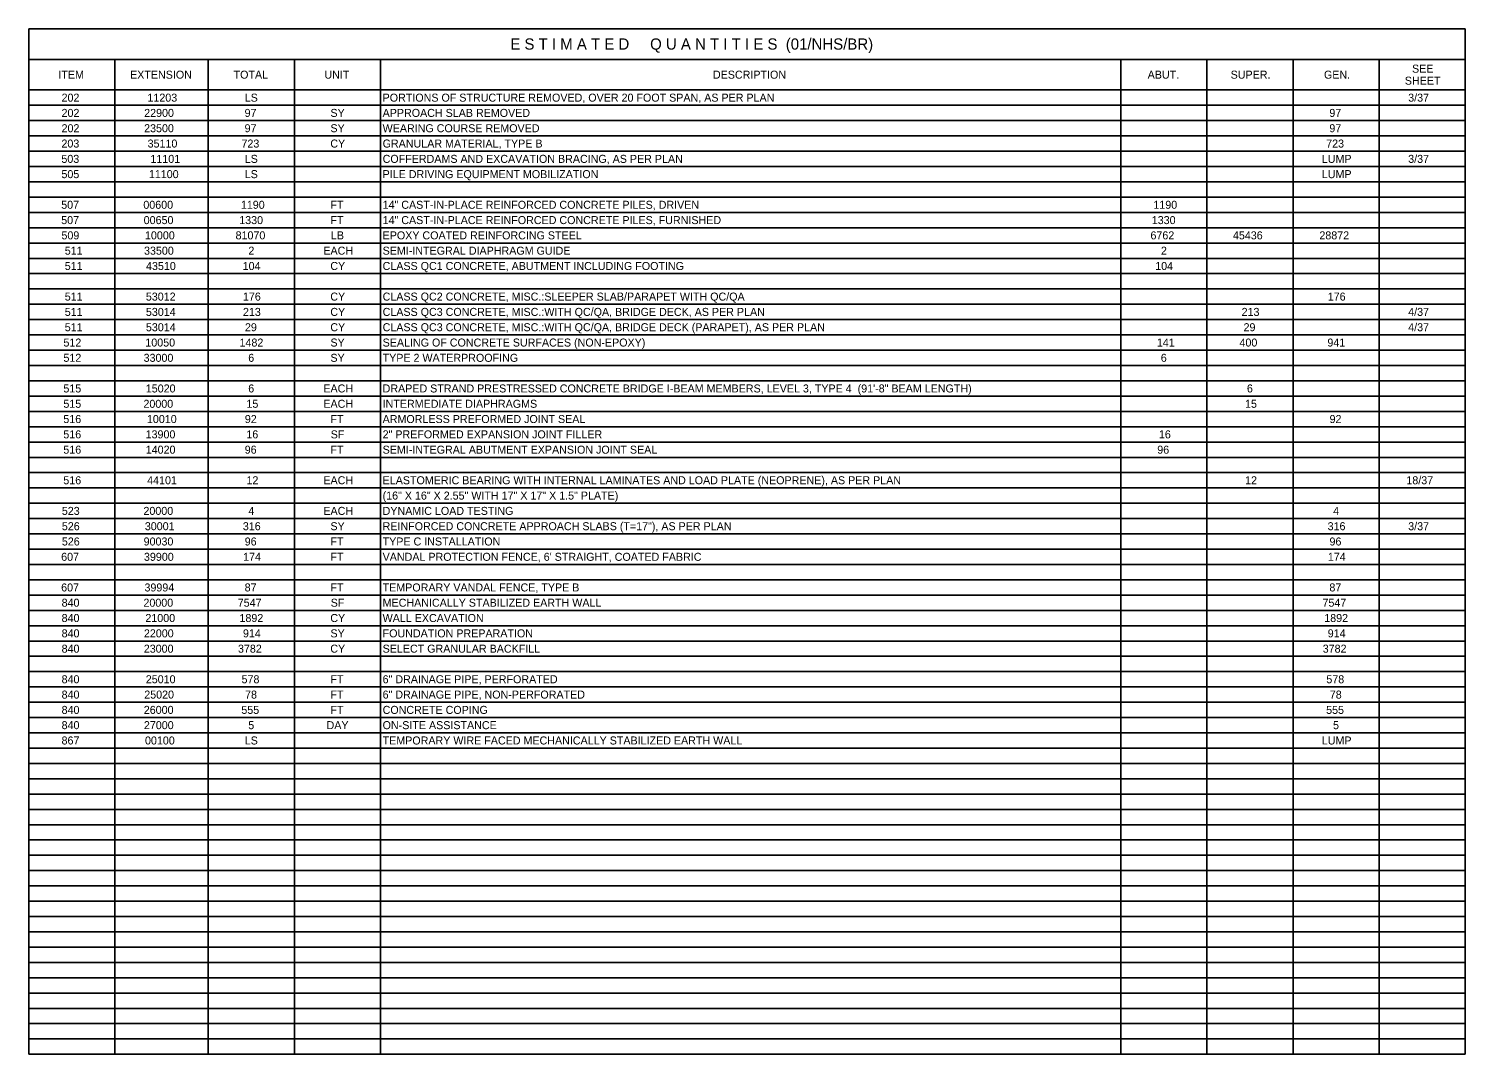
# Model space of a CAD drawing. Extents: x -1059 to 109, y -40 to 149.
# Drawn here: x -1059.2 to -1034.06, y 130.87 to 148.81 of the extents above; entities that cross this region are included whole.
import ezdxf

# ---------------------------------------------------------------- set-up
doc = ezdxf.new("R2010")
doc.units = 0
doc.layers.add('Sheet_Label_Str_Wt0', color=7, linetype='Continuous')

msp = doc.modelspace()

# ---------------------------------------------------------------- linework, layer by layer
at = {"layer": 'Sheet_Label_Str_Wt0'}
for p, q in [((-1059.195, 148.805), (-1059.195, 148.805)), ((-1059.195, 148.805), (-1034.058, 148.805)), ((-1059.195, 130.866), (-1059.195, 148.805)), ((-1034.058, 130.866), (-1034.058, 148.805)), ((-1059.195, 148.27), (-1034.058, 148.27)), ((-1057.689, 130.866), (-1057.689, 148.27)), ((-1056.053, 130.866), (-1056.053, 148.27)), ((-1054.547, 130.866), (-1054.547, 148.27)), ((-1053.04, 130.866), (-1053.04, 148.27)), ((-1040.085, 130.866), (-1040.085, 148.27)), ((-1038.579, 130.866), (-1038.579, 148.27)), ((-1037.072, 130.866), (-1037.072, 148.27)), ((-1035.565, 130.866), (-1035.565, 148.27)), ((-1059.195, 147.734), (-1034.058, 147.734)), ((-1059.195, 147.467), (-1034.058, 147.467)), ((-1059.195, 147.199), (-1034.058, 147.199)), ((-1059.195, 146.931), (-1034.058, 146.931)), ((-1059.195, 146.663), (-1034.058, 146.663)), ((-1059.195, 146.396), (-1034.058, 146.396)), ((-1059.195, 146.128), (-1034.058, 146.128)), ((-1059.195, 145.86), (-1034.058, 145.86)), ((-1059.195, 145.592), (-1034.058, 145.592)), ((-1059.195, 145.325), (-1034.058, 145.325)), ((-1059.195, 145.057), (-1034.058, 145.057)), ((-1059.195, 144.789), (-1034.058, 144.789)), ((-1059.195, 144.521), (-1034.058, 144.521)), ((-1059.195, 144.254), (-1034.058, 144.254)), ((-1059.195, 143.986), (-1034.058, 143.986)), ((-1059.195, 143.718), (-1034.058, 143.718)), ((-1059.195, 143.45), (-1034.058, 143.45)), ((-1059.195, 143.183), (-1034.058, 143.183)), ((-1059.195, 142.915), (-1034.058, 142.915)), ((-1059.195, 142.647), (-1034.058, 142.647)), ((-1059.195, 142.379), (-1034.058, 142.379)), ((-1059.195, 142.112), (-1034.058, 142.112)), ((-1059.195, 141.844), (-1034.058, 141.844)), ((-1059.195, 141.576), (-1034.058, 141.576)), ((-1059.195, 141.308), (-1034.058, 141.308)), ((-1059.195, 141.041), (-1034.058, 141.041)), ((-1059.195, 140.773), (-1034.058, 140.773)), ((-1059.195, 140.505), (-1034.058, 140.505)), ((-1059.195, 140.237), (-1034.058, 140.237)), ((-1059.195, 139.97), (-1034.058, 139.97)), ((-1059.195, 139.702), (-1034.058, 139.702)), ((-1059.195, 139.434), (-1034.058, 139.434)), ((-1059.195, 139.166), (-1034.058, 139.166)), ((-1059.195, 138.899), (-1034.058, 138.899)), ((-1059.195, 138.631), (-1034.058, 138.631)), ((-1059.195, 138.363), (-1034.058, 138.363)), ((-1059.195, 138.095), (-1034.058, 138.095)), ((-1059.195, 137.828), (-1034.058, 137.828)), ((-1059.195, 137.56), (-1034.058, 137.56)), ((-1059.195, 137.292), (-1034.058, 137.292)), ((-1059.195, 137.024), (-1034.058, 137.024)), ((-1059.195, 136.757), (-1034.058, 136.757)), ((-1059.195, 136.489), (-1034.058, 136.489)), ((-1059.195, 136.221), (-1034.058, 136.221)), ((-1059.195, 135.953), (-1034.058, 135.953)), ((-1059.195, 135.686), (-1034.058, 135.686)), ((-1059.195, 135.418), (-1034.058, 135.418)), ((-1059.195, 135.15), (-1034.058, 135.15)), ((-1059.195, 134.882), (-1034.058, 134.882)), ((-1059.195, 134.615), (-1034.058, 134.615)), ((-1059.195, 134.347), (-1034.058, 134.347)), ((-1059.195, 134.079), (-1034.058, 134.079)), ((-1059.195, 133.811), (-1034.058, 133.811)), ((-1059.195, 133.544), (-1034.058, 133.544)), ((-1059.195, 133.276), (-1034.058, 133.276)), ((-1059.195, 133.008), (-1034.058, 133.008)), ((-1059.195, 132.74), (-1034.058, 132.74)), ((-1059.195, 132.473), (-1034.058, 132.473)), ((-1059.195, 132.205), (-1034.058, 132.205)), ((-1059.195, 131.937), (-1034.058, 131.937)), ((-1059.195, 131.669), (-1034.058, 131.669)), ((-1059.195, 131.402), (-1034.058, 131.402)), ((-1059.195, 131.134), (-1034.058, 131.134)), ((-1059.195, 130.866), (-1034.058, 130.866))]:
    msp.add_line(p, q, dxfattribs=at)

# ---------------------------------------------------------------- texts
for s, height, p in [('E S T I M A T E D     Q U A N T I T I E S  (01/NHS/BR)', 0.196, (-1050.769, 148.44)), ('ITEM', 0.14, (-1058.676, 147.932)), ('EXTENSION', 0.14, (-1057.422, 147.932)), ('TOTAL', 0.14, (-1055.611, 147.932)), ('UNIT', 0.14, (-1054.022, 147.932)), ('DESCRIPTION', 0.14, (-1047.223, 147.932)), ('ABUT.', 0.14, (-1039.616, 147.932)), ('SUPER.', 0.14, (-1038.164, 147.932)), ('GEN.', 0.14, (-1036.531, 147.932)), ('SEE', 0.14, (-1034.99, 148.037)), ('SHEET', 0.14, (-1035.116, 147.827)), ('202', 0.14, (-1058.621, 147.53)), ('11203', 0.14, (-1057.118, 147.53)), ('LS', 0.14, (-1055.416, 147.53)), ('PORTIONS OF STRUCTURE REMOVED, OVER 20 FOOT SPAN, AS PER PLAN', 0.14, (-1053.003, 147.53)), ('3/37', 0.14, (-1035.057, 147.53)), ('202', 0.14, (-1058.621, 147.263)), ('22900', 0.14, (-1057.175, 147.263)), ('97', 0.14, (-1055.418, 147.263)), ('SY', 0.14, (-1053.916, 147.263)), ('APPROACH SLAB REMOVED', 0.14, (-1053.003, 147.263)), ('97', 0.14, (-1036.437, 147.263)), ('202', 0.14, (-1058.621, 146.995)), ('23500', 0.14, (-1057.176, 146.995)), ('97', 0.14, (-1055.418, 146.995)), ('SY', 0.14, (-1053.916, 146.995)), ('WEARING COURSE REMOVED', 0.14, (-1053.003, 146.995)), ('97', 0.14, (-1036.437, 146.995)), ('203', 0.14, (-1058.623, 146.727)), ('35110', 0.14, (-1057.115, 146.727)), ('723', 0.14, (-1055.473, 146.727)), ('CY', 0.14, (-1053.918, 146.727)), ('GRANULAR MATERIAL, TYPE B', 0.14, (-1053.003, 146.727)), ('723', 0.14, (-1036.492, 146.727)), ('503', 0.14, (-1058.624, 146.459)), ('11101', 0.14, (-1057.066, 146.459)), ('LS', 0.14, (-1055.416, 146.459)), ('COFFERDAMS AND EXCAVATION BRACING, AS PER PLAN', 0.14, (-1053.003, 146.459)), ('LUMP', 0.14, (-1036.569, 146.459)), ('3/37', 0.14, (-1035.057, 146.459)), ('505', 0.14, (-1058.623, 146.192)), ('11100', 0.14, (-1057.093, 146.192)), ('LS', 0.14, (-1055.416, 146.192)), ('PILE DRIVING EQUIPMENT MOBILIZATION', 0.14, (-1053.003, 146.192)), ('LUMP', 0.14, (-1036.569, 146.192)), ('507', 0.14, (-1058.627, 145.656)), ('00600', 0.14, (-1057.19, 145.656)), ('1190', 0.14, (-1055.483, 145.656)), ('FT', 0.14, (-1053.916, 145.656)), ('14" CAST-IN-PLACE REINFORCED CONCRETE PILES, DRIVEN', 0.14, (-1053.003, 145.656)), ('1190', 0.14, (-1039.516, 145.656)), ('507', 0.14, (-1058.627, 145.388)), ('00650', 0.14, (-1057.184, 145.388)), ('1330', 0.14, (-1055.512, 145.388)), ('FT', 0.14, (-1053.916, 145.388)), ('14" CAST-IN-PLACE REINFORCED CONCRETE PILES, FURNISHED', 0.14, (-1053.003, 145.388)), ('1330', 0.14, (-1039.544, 145.388)), ('509', 0.14, (-1058.623, 145.121)), ('10000', 0.14, (-1057.161, 145.121)), ('81070', 0.14, (-1055.576, 145.121)), ('LB', 0.14, (-1053.908, 145.121)), ('EPOXY COATED REINFORCING STEEL', 0.14, (-1053.003, 145.121)), ('6762', 0.14, (-1039.567, 145.121)), ('45436', 0.14, (-1038.124, 145.121)), ('28872', 0.14, (-1036.611, 145.121)), ('511', 0.14, (-1058.565, 144.853)), ('33500', 0.14, (-1057.178, 144.853)), ('2', 0.14, (-1055.352, 144.853)), ('EACH', 0.14, (-1054.04, 144.853)), ('SEMI-INTEGRAL DIAPHRAGM GUIDE', 0.14, (-1053.003, 144.853)), ('2', 0.14, (-1039.384, 144.853)), ('511', 0.14, (-1058.565, 144.585)), ('43510', 0.14, (-1057.143, 144.585)), ('104', 0.14, (-1055.452, 144.585)), ('CY', 0.14, (-1053.918, 144.585)), ('CLASS QC1 CONCRETE, ABUTMENT INCLUDING FOOTING', 0.14, (-1053.003, 144.585)), ('104', 0.14, (-1039.484, 144.585)), ('511', 0.14, (-1058.565, 144.05)), ('53012', 0.14, (-1057.146, 144.05)), ('176', 0.14, (-1055.447, 144.05)), ('CY', 0.14, (-1053.918, 144.05)), ('CLASS QC2 CONCRETE, MISC.:SLEEPER SLAB/PARAPET WITH QC/QA', 0.14, (-1053.003, 144.05)), ('176', 0.14, (-1036.465, 144.05)), ('511', 0.14, (-1058.565, 143.782)), ('53014', 0.14, (-1057.145, 143.782)), ('213', 0.14, (-1055.447, 143.782)), ('CY', 0.14, (-1053.918, 143.782)), ('CLASS QC3 CONCRETE, MISC.:WITH QC/QA, BRIDGE DECK, AS PER PLAN', 0.14, (-1053.003, 143.782)), ('213', 0.14, (-1037.972, 143.782)), ('4/37', 0.14, (-1035.057, 143.782)), ('511', 0.14, (-1058.565, 143.514)), ('53014', 0.14, (-1057.145, 143.514)), ('29', 0.14, (-1055.412, 143.514)), ('CY', 0.14, (-1053.918, 143.514)), ('CLASS QC3 CONCRETE, MISC.:WITH QC/QA, BRIDGE DECK (PARAPET), AS PER PLAN', 0.14, (-1053.003, 143.514)), ('29', 0.14, (-1037.938, 143.514)), ('4/37', 0.14, (-1035.057, 143.514)), ('512', 0.14, (-1058.588, 143.246)), ('10050', 0.14, (-1057.155, 143.246)), ('1482', 0.14, (-1055.507, 143.246)), ('SY', 0.14, (-1053.916, 143.246)), ('SEALING OF CONCRETE SURFACES (NON-EPOXY)', 0.14, (-1053.003, 143.246)), ('141', 0.14, (-1039.455, 143.246)), ('400', 0.14, (-1038.009, 143.246)), ('941', 0.14, (-1036.471, 143.246)), ('512', 0.14, (-1058.588, 142.979)), ('33000', 0.14, (-1057.185, 142.979)), ('6', 0.14, (-1055.354, 142.979)), ('SY', 0.14, (-1053.916, 142.979)), ('TYPE 2 WATERPROOFING', 0.14, (-1053.003, 142.979)), ('6', 0.14, (-1039.386, 142.979)), ('515', 0.14, (-1058.589, 142.443)), ('15020', 0.14, (-1057.147, 142.443)), ('6', 0.14, (-1055.354, 142.443)), ('EACH', 0.14, (-1054.04, 142.443)), ('DRAPED STRAND PRESTRESSED CONCRETE BRIDGE I-BEAM MEMBERS, LEVEL 3, TYPE 4  (91\'-8" BEAM LENGTH)', 0.14, (-1053.003, 142.443)), ('6', 0.14, (-1037.879, 142.443)), ('515', 0.14, (-1058.589, 142.175)), ('20000', 0.14, (-1057.188, 142.175)), ('15', 0.14, (-1055.386, 142.175)), ('EACH', 0.14, (-1054.04, 142.175)), ('INTERMEDIATE DIAPHRAGMS', 0.14, (-1053.003, 142.175)), ('15', 0.14, (-1037.912, 142.175)), ('516', 0.14, (-1058.59, 141.908)), ('10010', 0.14, (-1057.127, 141.908)), ('92', 0.14, (-1055.414, 141.908)), ('FT', 0.14, (-1053.916, 141.908)), ('ARMORLESS PREFORMED JOINT SEAL', 0.14, (-1053.003, 141.908)), ('92', 0.14, (-1036.433, 141.908)), ('516', 0.14, (-1058.59, 141.64)), ('13900', 0.14, (-1057.15, 141.64)), ('16', 0.14, (-1055.387, 141.64)), ('SF', 0.14, (-1053.912, 141.64)), ('2" PREFORMED EXPANSION JOINT FILLER', 0.14, (-1053.003, 141.64)), ('16', 0.14, (-1039.419, 141.64)), ('516', 0.14, (-1058.59, 141.372)), ('14020', 0.14, (-1057.148, 141.372)), ('96', 0.14, (-1055.416, 141.372)), ('FT', 0.14, (-1053.916, 141.372)), ('SEMI-INTEGRAL ABUTMENT EXPANSION JOINT SEAL', 0.14, (-1053.003, 141.372)), ('96', 0.14, (-1039.448, 141.372)), ('516', 0.14, (-1058.59, 140.837)), ('44101', 0.14, (-1057.123, 140.837)), ('12', 0.14, (-1055.385, 140.837)), ('EACH', 0.14, (-1054.04, 140.837)), ('ELASTOMERIC BEARING WITH INTERNAL LAMINATES AND LOAD PLATE (NEOPRENE), AS PER PLAN', 0.14, (-1053.003, 140.837)), ('12', 0.14, (-1037.911, 140.837)), ('18/37', 0.14, (-1035.089, 140.837)), ('(16" X 16" X 2.55" WITH 17" X 17" X 1.5" PLATE)', 0.14, (-1053.003, 140.569)), ('523', 0.14, (-1058.616, 140.301)), ('20000', 0.14, (-1057.188, 140.301)), ('4', 0.14, (-1055.352, 140.301)), ('EACH', 0.14, (-1054.04, 140.301)), ('DYNAMIC LOAD TESTING', 0.14, (-1053.003, 140.301)), ('4', 0.14, (-1036.37, 140.301)), ('526', 0.14, (-1058.616, 140.033)), ('30001', 0.14, (-1057.164, 140.033)), ('316', 0.14, (-1055.449, 140.033)), ('SY', 0.14, (-1053.916, 140.033)), ('REINFORCED CONCRETE APPROACH SLABS (T=17"), AS PER PLAN', 0.14, (-1053.003, 140.033)), ('316', 0.14, (-1036.467, 140.033)), ('3/37', 0.14, (-1035.057, 140.033)), ('526', 0.14, (-1058.616, 139.766)), ('90030', 0.14, (-1057.185, 139.766)), ('96', 0.14, (-1055.416, 139.766)), ('FT', 0.14, (-1053.916, 139.766)), ('TYPE C INSTALLATION', 0.14, (-1053.003, 139.766)), ('96', 0.14, (-1036.434, 139.766)), ('607', 0.14, (-1058.628, 139.498)), ('39900', 0.14, (-1057.179, 139.498)), ('174', 0.14, (-1055.444, 139.498)), ('FT', 0.14, (-1053.916, 139.498)), ("VANDAL PROTECTION FENCE, 6' STRAIGHT, COATED FABRIC", 0.14, (-1053.003, 139.498)), ('174', 0.14, (-1036.463, 139.498)), ('607', 0.14, (-1058.628, 138.962)), ('39994', 0.14, (-1057.17, 138.962)), ('87', 0.14, (-1055.417, 138.962)), ('FT', 0.14, (-1053.916, 138.962)), ('TEMPORARY VANDAL FENCE, TYPE B', 0.14, (-1053.003, 138.962)), ('87', 0.14, (-1036.436, 138.962)), ('840', 0.14, (-1058.62, 138.695)), ('20000', 0.14, (-1057.188, 138.695)), ('7547', 0.14, (-1055.538, 138.695)), ('SF', 0.14, (-1053.912, 138.695)), ('MECHANICALLY STABILIZED EARTH WALL', 0.14, (-1053.003, 138.695)), ('7547', 0.14, (-1036.557, 138.695)), ('840', 0.14, (-1058.62, 138.427)), ('21000', 0.14, (-1057.154, 138.427)), ('1892', 0.14, (-1055.508, 138.427)), ('CY', 0.14, (-1053.918, 138.427)), ('WALL EXCAVATION', 0.14, (-1053.003, 138.427)), ('1892', 0.14, (-1036.526, 138.427)), ('840', 0.14, (-1058.62, 138.159)), ('22000', 0.14, (-1057.18, 138.159)), ('914', 0.14, (-1055.447, 138.159)), ('SY', 0.14, (-1053.916, 138.159)), ('FOUNDATION PREPARATION', 0.14, (-1053.003, 138.159)), ('914', 0.14, (-1036.465, 138.159)), ('840', 0.14, (-1058.62, 137.891)), ('23000', 0.14, (-1057.182, 137.891)), ('3782', 0.14, (-1055.534, 137.891)), ('CY', 0.14, (-1053.918, 137.891)), ('SELECT GRANULAR BACKFILL', 0.14, (-1053.003, 137.891)), ('3782', 0.14, (-1036.553, 137.891)), ('840', 0.14, (-1058.62, 137.356)), ('25010', 0.14, (-1057.147, 137.356)), ('578', 0.14, (-1055.471, 137.356)), ('FT', 0.14, (-1053.916, 137.356)), ('6" DRAINAGE PIPE, PERFORATED', 0.14, (-1053.003, 137.356)), ('578', 0.14, (-1036.489, 137.356)), ('840', 0.14, (-1058.62, 137.088)), ('25020', 0.14, (-1057.174, 137.088)), ('78', 0.14, (-1055.41, 137.088)), ('FT', 0.14, (-1053.916, 137.088)), ('6" DRAINAGE PIPE, NON-PERFORATED', 0.14, (-1053.003, 137.088)), ('78', 0.14, (-1036.429, 137.088)), ('840', 0.14, (-1058.62, 136.82)), ('26000', 0.14, (-1057.182, 136.82)), ('555', 0.14, (-1055.475, 136.82)), ('FT', 0.14, (-1053.916, 136.82)), ('CONCRETE COPING', 0.14, (-1053.003, 136.82)), ('555', 0.14, (-1036.493, 136.82)), ('840', 0.14, (-1058.62, 136.553)), ('27000', 0.14, (-1057.18, 136.553)), ('5', 0.14, (-1055.353, 136.553)), ('DAY', 0.14, (-1053.984, 136.553)), ('ON-SITE ASSISTANCE', 0.14, (-1053.003, 136.553)), ('5', 0.14, (-1036.372, 136.553)), ('867', 0.14, (-1058.621, 136.285)), ('00100', 0.14, (-1057.161, 136.285)), ('LS', 0.14, (-1055.416, 136.285)), ('TEMPORARY WIRE FACED MECHANICALLY STABILIZED EARTH WALL', 0.14, (-1053.003, 136.285)), ('LUMP', 0.14, (-1036.569, 136.285))]:
    msp.add_text(s, height=height, dxfattribs=at).set_placement(p)

doc.saveas('drawing.dxf')
